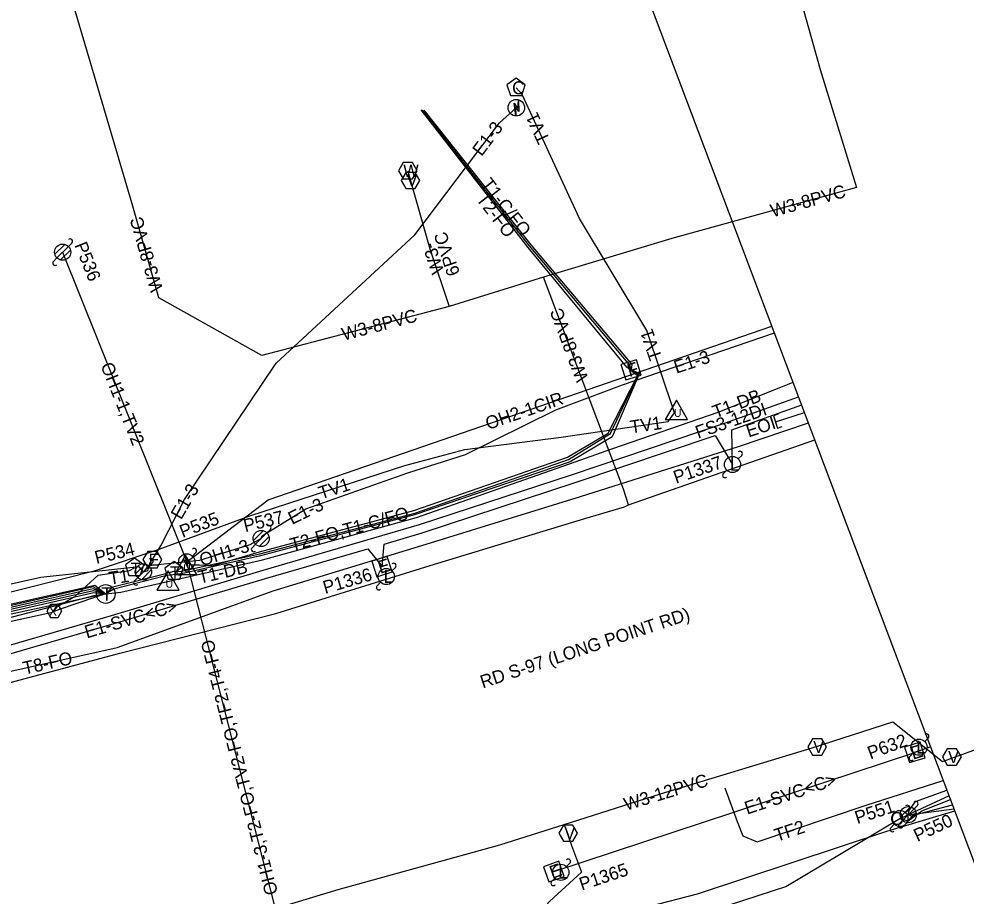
# Model space of a CAD drawing. Extents: x 2336688 to 2352634, y 362473 to 369571.
# Drawn here: x 2348250.9 to 2348543.2, y 367551 to 367821.8 of the extents above; entities that cross this region are included whole.
import ezdxf

# ---------------------------------------------------------------- set-up
doc = ezdxf.new("R2010")
doc.units = 0
for name, color, linetype in [('Default', 7, 'Continuous'), ('RD_EX_DV_Prop', 7, 'Continuous'), ('RD_EX_DV_TX_Prop', 7, 'Continuous'), ('RD_EX_RW', 7, 'Continuous'), ('RD_EX_RW_TX', 7, 'Continuous'), ('RD_HC_Data_Tic', 7, 'Continuous'), ('RD_PD_CstnLmt', 7, 'Continuous'), ('RD_PD_Final_TrvlWay', 7, 'Continuous'), ('RD_PD_FOC', 7, 'Continuous'), ('RD_PD_PatLn3', 7, 'Continuous'), ('RD_PD_PatLn4', 7, 'Continuous'), ('RD_SHT_ShtClip', 7, 'Continuous'), ('RD_Sketch1', 7, 'Continuous'), ('RD_Sketch2', 7, 'Continuous'), ('RD_Sketch5', 7, 'Continuous'), ('RD_Sketch8', 7, 'Continuous'), ('RD_TX_Misc1', 7, 'Continuous')]:
    doc.layers.add(name, color=color, linetype=linetype)

msp = doc.modelspace()

# ---------------------------------------------------------------- linework, layer by layer
at = {"layer": 'Default'}
msp.add_line((2348691.59, 367174.54), (2348367.83, 368033.25), dxfattribs=at)
msp.add_line((2348691.59, 367174.54), (2348367.83, 368033.25), dxfattribs=at)
msp.add_line((2348691.59, 367174.54), (2348367.83, 368033.25), dxfattribs=at)
at = {"layer": 'RD_EX_RW_TX'}
for points in [[(2347868.44, 368054.11), (2347880, 368005.49), (2347890.68, 367955.5), (2347902.22, 367909.33), (2347920.64, 367859.94), (2347940.18, 367812), (2347959.68, 367768.1), (2347973.8, 367721.46), (2347979.06, 367711.04), (2347991.9, 367664.85), (2347998.75, 367622.27), (2348003.55, 367586.06), (2348009.9, 367584.2), (2348035.07, 367585.97), (2348081.85, 367595.07), (2348134.22, 367608.61), (2348182.28, 367613.21), (2348234.44, 367617.29), (2348281.25, 367627.74), (2348329.4, 367645.16), (2348376.54, 367659.65), (2348424.27, 367674.35), (2348472.98, 367689.81), (2348494.58, 367697.07)], [(2348085.42, 367455.46), (2348085.25, 367456.81), (2348084.11, 367472.36), (2348078.05, 367492.84), (2348059.44, 367571.03), (2348057.43, 367578.05), (2348054.24, 367593.15), (2348053.27, 367598.58), (2348079.95, 367605.18), (2348132.88, 367615.72), (2348177.98, 367626.63), (2348230.33, 367640.4), (2348274.48, 367651.48), (2348294.14, 367658.1), (2348322.12, 367668.38), (2348370.04, 367683.85), (2348388.49, 367688.84), (2348418.25, 367692.63), (2348451.32, 367697.47), (2348453.28, 367700.17), (2348444.65, 367725.62), (2348423.89, 367760.2), (2348406.22, 367798.41), (2348404.33, 367800.52)], [(2348375.85, 367793.59), (2348408.93, 367751.98), (2348440.03, 367715.05), (2348439.84, 367713.42), (2348442.4, 367712.44), (2348433.97, 367692.76), (2348421.04, 367685.06), (2348373.32, 367668.79), (2348325.45, 367655.97), (2348301.02, 367650.46), (2348296.49, 367649.9), (2348280.18, 367645.7), (2348277.67, 367644.22), (2348273.75, 367646.44), (2348227.32, 367635.79)], [(2348227.72, 367634.18), (2348273.97, 367644.64), (2348277.67, 367644.22), (2348279.86, 367646.42), (2348296.18, 367650.52), (2348298.75, 367651.26), (2348300.68, 367651.15), (2348325.24, 367656.57), (2348373.1, 367669.22), (2348420.53, 367685.71), (2348433.52, 367693.8), (2348442.13, 367712.03), (2348439.84, 367713.42), (2348439.41, 367714.91), (2348408.52, 367751.69), (2348375.46, 367793.63)], [(2348302.69, 367654.16), (2348304.05, 367653.27), (2348306.57, 367653.27), (2348310.53, 367652.87), (2348325.15, 367657.23), (2348372.78, 367669.99), (2348420.25, 367686.5), (2348432.78, 367693.92), (2348441.83, 367711.59), (2348438.52, 367714.3), (2348408.11, 367751.18), (2348374.99, 367793.76)], [(2348277.67, 367644.22), (2348282.3, 367644.76), (2348326.11, 367654.73), (2348373.61, 367667.85), (2348420.87, 367684.45), (2348433.87, 367689.03), (2348466.99, 367700.5), (2348489.86, 367709.64)], [(2348261.8, 367638.98), (2348262.83, 367640.36), (2348268.1, 367643.4), (2348275.33, 367650), (2348285.01, 367651.5), (2348286.59, 367652.33)], [(2347889.37, 367561.99), (2347893.86, 367561.38), (2347925.12, 367563.83), (2347982.59, 367581.19), (2348034.77, 367589.67), (2348080.01, 367601.39), (2348132.99, 367613.3), (2348178.17, 367624.37), (2348226.99, 367636.38), (2348274.33, 367646.97), (2348277.67, 367644.22)], [(2348277.67, 367644.22), (2348273.99, 367643.66), (2348228.58, 367631.8), (2348180.44, 367618.2), (2348135.72, 367603.5), (2348082.46, 367593.52), (2348035.48, 367584.74), (2347984.84, 367574.01), (2347951.44, 367567.02), (2347939.95, 367565.03), (2347935.77, 367564.67), (2347885.73, 367554.51), (2347837.63, 367544.73), (2347786.79, 367534.85), (2347738.82, 367525.14), (2347722.47, 367522.46), (2347720.16, 367522.7), (2347718.41, 367521.27), (2347687.23, 367515.7), (2347639.77, 367505.05), (2347596.04, 367494.09), (2347543.53, 367483.61), (2347493.77, 367474.07), (2347444.64, 367465.68)], [(2348277.67, 367644.22), (2348274.19, 367643.16), (2348263.65, 367639.56), (2348260.75, 367638.41), (2348228.6, 367631.4), (2348180.48, 367617.57), (2348135.89, 367603.05), (2348082.6, 367592.95), (2348035.55, 367584.09), (2347984.98, 367573.4), (2347951.16, 367566.33), (2347935.9, 367564.13), (2347885.75, 367553.87), (2347837.61, 367543.77), (2347786.94, 367534.28), (2347738.95, 367524.48), (2347722.65, 367521.86), (2347718.4, 367520.47), (2347687.46, 367515.07), (2347596.2, 367493.52), (2347543.48, 367483.07), (2347493.75, 367473.66), (2347444.81, 367465.06)], [(2348277.67, 367644.22), (2348273.84, 367645.8), (2348227.29, 367635.33), (2348178.6, 367623.03), (2348133.33, 367611.87), (2348080.21, 367600.2), (2348034.92, 367588.57), (2348009.29, 367585.15), (2347982.98, 367580.09), (2347935.21, 367568.08), (2347896.24, 367563.27), (2347883.18, 367561.78), (2347837.9, 367550.42), (2347785.45, 367539.42), (2347739.83, 367529.65), (2347687.13, 367520.3), (2347638.22, 367510.11), (2347594.98, 367500.2), (2347542.99, 367489.7), (2347493.07, 367480.59), (2347455.62, 367474.3)], [(2348277.67, 367644.22), (2348227.84, 367633.58), (2348178.94, 367621.43), (2348133.69, 367610.27), (2348080.57, 367598.27), (2348068.66, 367596.86), (2348066.5, 367591.91), (2348067.19, 367583.21), (2348069.73, 367573.23), (2348081.3, 367522.36), (2348088.83, 367494.16)], [(2348227.7, 367634.92), (2348273.91, 367645.31), (2348277.67, 367644.22)], [(2348525.4, 367576.08), (2348525.66, 367577.36), (2348527.58, 367580.13), (2348537.32, 367583.7)], [(2348522.81, 367574.9), (2348525.41, 367574.14), (2348529.62, 367577.26), (2348538.42, 367580.79)], [(2348359.53, 367524.74), (2348362.5, 367525.55), (2348390.35, 367536.41), (2348407.13, 367542.05), (2348430.08, 367543.86), (2348460.37, 367551.68), (2348518.82, 367570.97), (2348539.75, 367577.27)]]:
    msp.add_lwpolyline(points, dxfattribs=at)
for points in [[(2348404.33, 367803.52), (2348401.48, 367801.45), (2348402.57, 367798.09), (2348406.1, 367798.09), (2348407.19, 367801.45)], [(2348441.5, 367716.54), (2348436.72, 367715.09), (2348438.18, 367710.3), (2348442.96, 367711.76)], [(2348286.59, 367655.33), (2348283.74, 367653.26), (2348284.83, 367649.9), (2348288.35, 367649.9), (2348289.44, 367653.26)], [(2348298.75, 367654.26), (2348295.9, 367652.19), (2348296.99, 367648.83), (2348300.52, 367648.83), (2348301.61, 367652.19)], [(2348259.49, 367638.98), (2348260.65, 367636.98), (2348262.95, 367636.98), (2348264.11, 367638.98), (2348262.95, 367640.98), (2348260.65, 367640.98)]]:
    msp.add_lwpolyline(points, close=True, dxfattribs=at)
msp.add_circle((2348277.67, 367644.22), 2.89, dxfattribs=at)
at = {"layer": 'RD_HC_Data_Tic'}
for p, q in [((2348265.02, 367752.17), (2348261.96, 367749.11)), ((2348267.2, 367752.59), (2348266.14, 367751.53)), ((2348266.14, 367751.53), (2348262.6, 367747.99)), ((2348266.79, 367750.41), (2348263.72, 367747.35)), ((2348262.6, 367747.99), (2348261.54, 367746.93)), ((2348472.91, 367685.97), (2348473.97, 367687.03)), ((2348468.31, 367681.38), (2348469.37, 367682.44)), ((2348326.31, 367663.76), (2348323.25, 367660.7)), ((2348327.43, 367663.11), (2348323.89, 367659.58)), ((2348328.08, 367661.99), (2348325.01, 367658.93)), ((2348328.49, 367664.18), (2348327.43, 367663.11)), ((2348323.89, 367659.58), (2348322.83, 367658.52)), ((2348305.52, 367656.99), (2348304.45, 367655.93)), ((2348286.9, 367650.41), (2348289.96, 367653.47)), ((2348287.55, 367649.29), (2348291.08, 367652.83)), ((2348291.08, 367652.83), (2348292.14, 367653.89)), ((2348288.67, 367648.64), (2348291.73, 367651.7)), ((2348300.92, 367652.39), (2348299.86, 367651.33)), ((2348366.03, 367651.36), (2348367.09, 367652.43)), ((2348286.48, 367648.23), (2348287.55, 367649.29)), ((2348361.43, 367646.77), (2348362.49, 367647.83)), ((2348530.47, 367598.67), (2348531.53, 367599.74)), ((2348525.87, 367594.08), (2348526.93, 367595.14)), ((2348526.05, 367578.49), (2348522.98, 367575.43)), ((2348527.17, 367577.84), (2348523.63, 367574.31)), ((2348525.64, 367577.73), (2348524.58, 367576.67)), ((2348527.81, 367576.72), (2348524.75, 367573.66)), ((2348528.23, 367578.91), (2348527.17, 367577.84)), ((2348523.63, 367574.31), (2348522.57, 367573.25)), ((2348521.04, 367573.13), (2348519.98, 367572.07)), ((2348419.9, 367560.05), (2348420.96, 367561.11)), ((2348415.3, 367555.46), (2348416.36, 367556.52))]:
    msp.add_line(p, q, dxfattribs=at)
msp.add_lwpolyline([(2348303.08, 367652.15), (2348302.25, 367654.16), (2348303.71, 367653.36), (2348301.84, 367656.04), (2348301.84, 367656.04), (2348303.04, 367653.95), (2348301.66, 367654.75)], close=True, dxfattribs=at)
for centre in [(2348264.37, 367749.76), (2348471.14, 367684.2), (2348325.66, 367661.35), (2348302.69, 367654.16), (2348289.31, 367651.06), (2348364.26, 367649.6), (2348528.7, 367596.91), (2348522.81, 367574.9), (2348525.4, 367576.08), (2348418.13, 367558.29)]:
    msp.add_circle(centre, 2.5, dxfattribs=at)
for centre, start, end in [((2348266.67, 367753.12), 315, 135), ((2348262.07, 367746.4), 135, 315), ((2348473.44, 367687.56), 315, 135), ((2348468.84, 367680.85), 135, 315), ((2348327.96, 367664.71), 315, 135), ((2348323.36, 367657.99), 135, 315), ((2348304.99, 367657.52), 315, 135), ((2348291.61, 367654.42), 315, 135), ((2348366.56, 367652.96), 315, 135), ((2348300.39, 367650.8), 135, 315), ((2348287.02, 367647.7), 135, 315), ((2348361.96, 367646.24), 135, 315), ((2348531, 367600.27), 315, 135), ((2348526.4, 367593.55), 135, 315), ((2348527.7, 367579.44), 315, 135), ((2348525.11, 367578.26), 315, 135), ((2348520.51, 367571.54), 135, 315), ((2348523.1, 367572.72), 135, 315), ((2348420.43, 367561.64), 315, 135), ((2348415.83, 367554.93), 135, 315)]:
    msp.add_arc(centre, 0.75, start, end, dxfattribs=at)
at = {"layer": 'RD_PD_Final_TrvlWay'}
msp.add_line((2348415.98, 367558.5), (2348527.42, 367595.3), dxfattribs=at)
for points in [[(2348405.09, 367796.74), (2348405.18, 367793.15), (2348404.14, 367794.78), (2348404.26, 367791.85), (2348403.74, 367795.79), (2348404.86, 367794.11)], [(2348294.95, 367654.82), (2348293.5, 367657.32), (2348290.62, 367657.32), (2348289.17, 367654.82), (2348290.62, 367652.32), (2348293.5, 367652.32)], [(2348364.59, 367655.82), (2348359.83, 367654.32), (2348361.33, 367649.55), (2348366.1, 367651.05)], [(2348529.03, 367598.44), (2348524.28, 367596.91), (2348525.81, 367592.15), (2348530.57, 367593.68)], [(2348417.49, 367561.7), (2348412.78, 367560.01), (2348414.47, 367555.3), (2348419.18, 367556.99)]]:
    msp.add_lwpolyline(points, close=True, dxfattribs=at)
for points in [[(2348289.31, 367651.06), (2348290.62, 367651.43), (2348291.43, 367653.99), (2348292.06, 367654.82), (2348294.81, 367659.28), (2348301.95, 367673.36), (2348330.25, 367715.5), (2348373.05, 367755.15), (2348399.18, 367789.73), (2348404.4, 367794.36)], [(2348325.66, 367661.35), (2348325.95, 367662.15), (2348339.42, 367670.54), (2348370.97, 367681.63), (2348388.73, 367687.32), (2348416.58, 367701.13), (2348437.19, 367708.83), (2348484.13, 367724.88)], [(2348031.3, 367574.69), (2348041.95, 367577.13), (2348125.66, 367593.48), (2348129.45, 367589.55), (2348125.72, 367590.29), (2348132.8, 367597.05), (2348137.17, 367597.99), (2348182.97, 367609.24), (2348233.43, 367621.44), (2348242.25, 367624.01), (2348245.58, 367620.04), (2348246.3, 367625.19), (2348280.23, 367635.06), (2348327.01, 367648.97), (2348358.59, 367658.19), (2348362.96, 367652.69), (2348363.57, 367659.64), (2348375.35, 367663.08), (2348422.56, 367678.6), (2348465.74, 367693.2), (2348471.14, 367684.2), (2348470.93, 367694.95), (2348492.5, 367702.58)], [(2348532.32, 367596.98), (2348527.42, 367595.3)], [(2348525.4, 367576.08), (2348526.24, 367575.73), (2348539.06, 367579.1)]]:
    msp.add_lwpolyline(points, dxfattribs=at)
msp.add_circle((2348404.4, 367794.36), 2.55, dxfattribs=at)
at = {"layer": 'RD_PD_FOC'}
msp.add_lwpolyline([(2348485.19, 367699.72), (2348483.76, 367699.25), (2348485, 367695.45), (2348486.43, 367695.92)], dxfattribs=at)
at = {"layer": 'RD_PD_PatLn3'}
for points in [[(2348453.83, 367704.1), (2348450.37, 367698.1), (2348457.3, 367698.1)], [(2348302.34, 367656.21), (2348298.88, 367650.21), (2348305.8, 367650.21)], [(2348296.9, 367651.38), (2348293.43, 367645.38), (2348300.36, 367645.38)]]:
    msp.add_lwpolyline(points, close=True, dxfattribs=at)
at = {"layer": 'RD_SHT_ShtClip'}
for p, q in [((2348264.37, 367749.76), (2348302.69, 367654.16)), ((2348338.28, 367514.83), (2348302.69, 367654.16)), ((2348537.99, 367581.94), (2348525.4, 367576.08)), ((2348522.81, 367574.9), (2348525.4, 367576.08))]:
    msp.add_line(p, q, dxfattribs=at)
for points in [[(2348302.69, 367654.16), (2348327.8, 367673.26), (2348483.33, 367726.9)], [(2348325.66, 367661.35), (2348322.15, 367659.44), (2348306.66, 367654.6), (2348302.69, 367654.16)], [(2348302.69, 367654.16), (2348290.76, 367652.88), (2348289.31, 367651.06), (2348287.96, 367652.58), (2348257.65, 367649.33), (2348056.6, 367604.27), (2348013.81, 367589.41)], [(2348525.4, 367576.08), (2348539.52, 367577.89)], [(2348338.28, 367514.83), (2348379.11, 367518.63), (2348487.57, 367553.93), (2348522.81, 367574.9)]]:
    msp.add_lwpolyline(points, dxfattribs=at)
at = {"layer": 'RD_Sketch2'}
for points in [[(2348556.24, 367909.26), (2348552.57, 367908), (2348533.51, 367902.75), (2348495.8, 367890.75), (2348476.22, 367884.91), (2348498.22, 367806.14), (2348509.39, 367769.77), (2348452.39, 367753.96), (2348412.83, 367742.03), (2348383.64, 367733), (2348325.81, 367717.84), (2348294.09, 367735.62), (2348285.99, 367763.92), (2348272.89, 367808.65), (2348260.35, 367851.09), (2348247.19, 367895.19), (2348233.68, 367941.56), (2348220.7, 367989.93), (2348226.95, 367991.6), (2348244.37, 367996.56), (2348246.31, 367997.03), (2348247.28, 367997.26)], [(2348370.91, 367774.9), (2348371.48, 367772.88), (2348377.68, 367750.83), (2348383.64, 367733)], [(2348439.07, 367671.71), (2348437.54, 367676.56), (2348412.83, 367742.03)], [(2348233.5, 367612.99), (2348282.05, 367625.96), (2348330.19, 367638.15), (2348377.81, 367652.99), (2348425.55, 367667.56), (2348437.8, 367671.1), (2348439.07, 367671.71), (2348474.46, 367684.15), (2348496.55, 367691.85)], [(2348204.32, 367511.65), (2348252.13, 367524.59), (2348302.77, 367538.93), (2348349.4, 367552.98), (2348399.28, 367566.78), (2348419.19, 367573.03), (2348448.96, 367582.56), (2348495.7, 367596.69), (2348520.67, 367604.71), (2348535.97, 367592.48), (2348556.39, 367599.86), (2348601.65, 367616.49)], [(2348419.19, 367573.03), (2348421.47, 367566.58), (2348424.48, 367558.37), (2348414.74, 367549.36), (2348401.01, 367534.36), (2348406.6, 367507.53), (2348416.22, 367458.49), (2348427.29, 367409.06), (2348435.75, 367372.22)]]:
    msp.add_lwpolyline(points, dxfattribs=at)
for points in [[(2348373.8, 367774.9), (2348372.36, 367777.4), (2348369.47, 367777.4), (2348368.03, 367774.9), (2348369.47, 367772.4), (2348372.36, 367772.4)], [(2348374.64, 367771.92), (2348373.2, 367774.41), (2348370.31, 367774.41), (2348368.87, 367771.92), (2348370.31, 367769.42), (2348373.2, 367769.42)], [(2348500.13, 367597), (2348498.69, 367599.5), (2348495.8, 367599.5), (2348494.36, 367597), (2348495.8, 367594.5), (2348498.69, 367594.5)], [(2348541.78, 367593.9), (2348540.33, 367596.4), (2348537.45, 367596.4), (2348536, 367593.9), (2348537.45, 367591.4), (2348540.33, 367591.4)], [(2348423.34, 367570.39), (2348421.9, 367572.89), (2348419.01, 367572.89), (2348417.57, 367570.39), (2348419.01, 367567.89), (2348421.9, 367567.89)]]:
    msp.add_lwpolyline(points, close=True, dxfattribs=at)
at = {"layer": 'RD_Sketch5'}
msp.add_lwpolyline([(2347445.27, 367463.42), (2347494.44, 367469.25), (2347544.4, 367476.73), (2347594.33, 367486.36), (2347688.22, 367508.14), (2347739.9, 367520.09), (2347788.33, 367529.45), (2347838.31, 367540.64), (2347886.7, 367551.33), (2347928.19, 367559.84), (2347952.54, 367563.69), (2347985.72, 367570.62), (2348036.5, 367580.92), (2348083.37, 367589.22), (2348136.57, 367600.6), (2348182.34, 367611.84), (2348232.74, 367624.03), (2348279.47, 367637.63), (2348326.25, 367651.54), (2348374.55, 367665.64), (2348421.71, 367681.15), (2348468.93, 367697.05), (2348491.54, 367705.13)], dxfattribs=at)
at = {"layer": 'RD_Sketch8'}
for points in [[(2348484.38, 367697.35), (2348493.37, 367700.29)], [(2348468.74, 367584.4), (2348472.54, 367574.02), (2348474.3, 367569.6), (2348478.8, 367567.73), (2348512.41, 367579.03), (2348536.2, 367586.68)]]:
    msp.add_lwpolyline(points, dxfattribs=at)

# ---------------------------------------------------------------- texts
at = {"layer": 'RD_EX_DV_Prop'}
for s, rotation, p in [('E1-3', 52.9236, (2348393.69, 367779.14)), ('E1-3', 18.3082, (2348453.82, 367712.23)), ('E1-3', 59.7846, (2348300.94, 367666.94)), ('E1-3', 25.9152, (2348335.18, 367665.55)), ('E1-SVC<C>', 16.5588, (2348271.84, 367630.48)), ('E1-SVC<C>', 18.2724, (2348475.64, 367576.09))]:
    msp.add_text(s, height=4, rotation=rotation, dxfattribs=at).set_placement(p)
at = {"layer": 'RD_EX_DV_TX_Prop'}
for s, rotation, p in [('P536', 291.8397, (2348267.95, 367751.97)), ('P1337', 18.6739, (2348453.7, 367678.24)), ('P535', 21.024, (2348301.4, 367661.48)), ('P537', 13.4802, (2348320.73, 367663.29)), ('P534', 13.4802, (2348274.79, 367653.46)), ('P1336', 16.2723, (2348345.39, 367644.22)), ('P632', 20.31, (2348513.7, 367593.11)), ('P551', 18.0321, (2348509.66, 367573.14)), ('P550', 24.9699, (2348528.21, 367567.61)), ('P1365', 18.2724, (2348424.61, 367552.63))]:
    msp.add_text(s, height=4, rotation=rotation, dxfattribs=at).set_placement(p)
at = {"layer": 'RD_EX_RW'}
for s, rotation, p in [('TV1', 114.8071, (2348414.9, 367784.4)), ('T1-C/FO', 307.8774, (2348393.33, 367770.7)), ('T2-FO', 307.8774, (2348391.82, 367766.06)), ('TV1', 108.7376, (2348449.47, 367717.16)), ('T1-DB', 20.6045, (2348465.89, 367698.41)), ('TV1', 8.3247, (2348439.83, 367693.77)), ('TV1', 17.8967, (2348344.13, 367673.37)), ('T2-FO,T1-C/FO', 15.413, (2348335.2, 367657.4)), ('T1-DB', 12.8265, (2348306.69, 367647.38)), ('T1', 8.7906, (2348278.93, 367647.04)), ('T8-FO', 12.5812, (2348252.6, 367619.29))]:
    msp.add_text(s, height=4, rotation=rotation, dxfattribs=at).set_placement(p)
at = {"layer": 'RD_EX_RW_TX'}
for s, height, p in [('C', 4, (2348403.11, 367798.52)), ('T', 3.75, (2348285.36, 367650.1)), ('T', 3.75, (2348297.52, 367649.03)), ('T', 4.12, (2348276.34, 367642.16))]:
    msp.add_text(s, height=height, dxfattribs=at).set_placement(p)
for s, height, rotation, p in [('F', 4, 16.9682, (2348439.34, 367711.18)), ('X', 3, 180, (2348262.74, 367640.48))]:
    msp.add_text(s, height=height, rotation=rotation, dxfattribs=at).set_placement(p)
at = {"layer": 'RD_HC_Data_Tic'}
for s, rotation, p in [('L', 360, (2348470.33, 367682.27)), ('L', 360, (2348363.45, 367647.66)), ('L', 360, (2348527.89, 367594.97)), ('O', 180, (2348524.1, 367576.9)), ('L', 360, (2348417.32, 367556.35))]:
    msp.add_text(s, height=4, rotation=rotation, dxfattribs=at).set_placement(p)
at = {"layer": 'RD_PD_CstnLmt'}
for s, rotation, p in [('W3-8PVC', 15.5047, (2348483.51, 367760.51)), ('W3-8PVC', 105.9719, (2348295.43, 367738.19)), ('6PVC', 108.4658, (2348387.08, 367743.19)), ('W3-', 108.4658, (2348382.23, 367743.81)), ('W3-8PVC', 14.6915, (2348351.12, 367722.41)), ('W3-8PVC', 110.6765, (2348426.8, 367710.67)), ('W3-12PVC', 16.821, (2348438.34, 367577.26))]:
    msp.add_text(s, height=4, rotation=rotation, dxfattribs=at).set_placement(p)
at = {"layer": 'RD_PD_Final_TrvlWay'}
for height, rotation, p in [(3.75, 360, (2348290.92, 367652.94)), (4, 17.5359, (2348362.41, 367650.41)), (4, 17.8814, (2348526.88, 367593.02)), (4, 19.7582, (2348415.51, 367556.21))]:
    msp.add_text('E', height=height, rotation=rotation, dxfattribs=at).set_placement(p)
at = {"layer": 'RD_PD_FOC'}
for s, rotation, p in [('EOI', 18.1179, (2348476.1, 367692.54)), ('TF2', 18.4113, (2348484.84, 367567.69))]:
    msp.add_text(s, height=4, rotation=rotation, dxfattribs=at).set_placement(p)
at = {"layer": 'RD_PD_PatLn3'}
for p in [(2348453.08, 367698.9), (2348301.58, 367651.01), (2348296.14, 367646.18)]:
    msp.add_text('U', height=2.4, dxfattribs=at).set_placement(p)
at = {"layer": 'RD_PD_PatLn4'}
for s, rotation, p in [('OH1-1,TV2', 291.8397, (2348276, 367714.79)), ('OH2-1CIR', 19.0295, (2348395.71, 367694.85)), ('OH1-3', 17.3752, (2348307.32, 367652.71)), ('OH1-3,T2-FO,TV2-FO,TF2,T4-FO', 104.3299, (2348330.89, 367551.84))]:
    msp.add_text(s, height=4, rotation=rotation, dxfattribs=at).set_placement(p)
at = {"layer": 'RD_Sketch1'}
msp.add_text('FS3-12DI', height=4, rotation=19.2256, dxfattribs=at).set_placement((2348460.51, 367692.11))
at = {"layer": 'RD_Sketch2'}
for s, p in [('W', (2348369.53, 367773.02)), ('V', (2348370.54, 367770.04)), ('V', (2348496.03, 367595.13)), ('V', (2348537.68, 367592.02)), ('V', (2348419.25, 367568.51))]:
    msp.add_text(s, height=3.75, dxfattribs=at).set_placement(p)
at = {"layer": 'RD_TX_Misc1'}
msp.add_text('RD S-97 (LONG POINT RD)', height=4, rotation=18.346, dxfattribs=at).set_placement((2348394.05, 367615.05))

doc.saveas('drawing.dxf')
